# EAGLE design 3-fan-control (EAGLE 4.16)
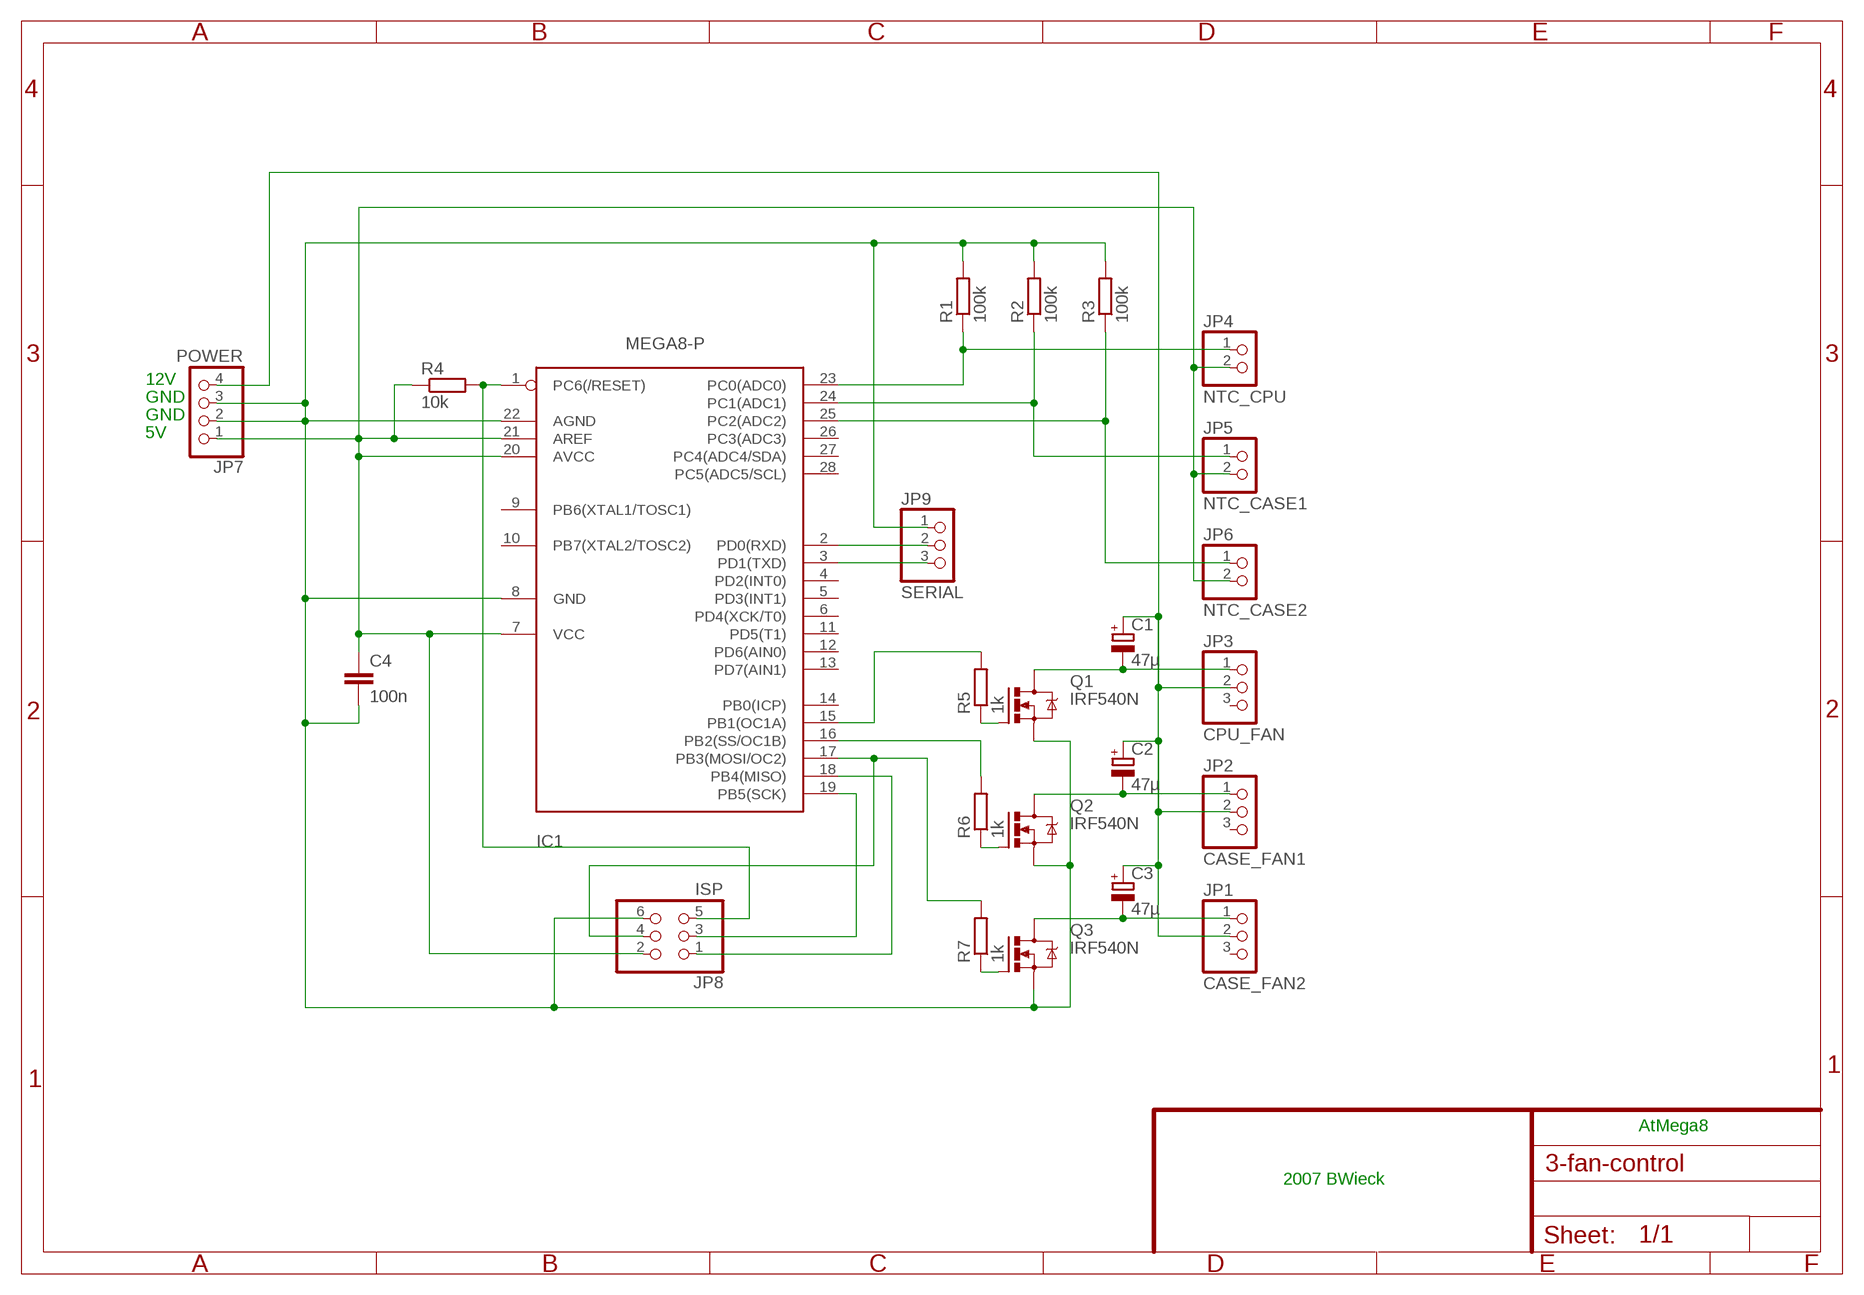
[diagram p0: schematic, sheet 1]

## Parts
C1  47µ  CPOL-EUE5-10.5  [E5-10,5]
C2  47µ  CPOL-EUE5-10.5  [E5-10,5]
C3  47µ  CPOL-EUE5-10.5  [E5-10,5]
C4  100n  C-EU050-024X044  [C050-024X044]
IC1  MEGA8-P  [DIL28-3]
JP1  CASE_FAN2  PINHD-1X3  [1X03]
JP2  CASE_FAN1  PINHD-1X3  [1X03]
JP3  CPU_FAN  PINHD-1X3  [1X03]
JP4  NTC_CPU  PINHD-1X2  [1X02]
JP5  NTC_CASE1  PINHD-1X2  [1X02]
JP6  NTC_CASE2  PINHD-1X2  [1X02]
JP7  POWER  PINHD-1X4  [1X04]
JP8  ISP  PINHD-2X3  [2X03]
JP9  SERIAL  PINHD-1X3  [1X03]
Q1  IRF540N  IRF740  [TO220BV]
Q2  IRF540N  IRF740  [TO220BV]
Q3  IRF540N  IRF740  [TO220BV]
R1  100k  R-EU_0207/10  [0207/10]
R2  100k  R-EU_0207/10  [0207/10]
R3  100k  R-EU_0207/10  [0207/10]
R4  10k  R-EU_0207/10  [0207/10]
R5  1k  R-EU_0207/10  [0207/10]
R6  1k  R-EU_0207/10  [0207/10]
R7  1k  R-EU_0207/10  [0207/10]

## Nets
N$1: C4.1 IC1.7(VCC) IC1.20(AVCC) IC1.21(AREF) JP4.2 JP5.2 JP6.2 JP7.1 JP8.2 R4.1
N$2: IC1.15(PB1(OC1A)) R5.2
N$3: IC1.1(PC6(/RESET)) JP8.5 R4.2
N$4: Q3.G R7.1
N$5: IC1.23(PC0(ADC0)) JP4.1 R1.1
N$6: IC1.24(PC1(ADC1)) JP5.1 R2.1
N$7: IC1.25(PC2(ADC2)) JP6.1 R3.1
N$8: C4.2 IC1.8(GND) IC1.22(AGND) JP7.2 JP7.3 JP8.6 JP9.1 Q1.S Q2.S Q3.S R1.2 R2.2 R3.2
N$9: C1.+ C2.+ C3.+ JP1.2 JP2.2 JP3.2 JP7.4
N$10: C1.- JP3.1 Q1.D
N$11: C2.- JP2.1 Q2.D
N$12: C3.- JP1.1 Q3.D
N$13: IC1.18(PB4(MISO)) JP8.1
N$14: IC1.19(PB5(SCK)) JP8.3
N$15: IC1.16(PB2(SS/OC1B)) R6.2
N$16: Q1.G R5.1
N$18: Q2.G R6.1
N$19: IC1.17(PB3(MOSI/OC2)) JP8.4 R7.2
N$21: IC1.3(PD1(TXD)) JP9.3
N$22: IC1.2(PD0(RXD)) JP9.2
Unconnected: IC1.4(PD2(INT0)) IC1.5(PD3(INT1)) IC1.6(PD4(XCK/T0)) IC1.9(PB6(XTAL1/TOSC1)) IC1.10(PB7(XTAL2/TOSC2)) IC1.11(PD5(T1)) IC1.12(PD6(AIN0)) IC1.13(PD7(AIN1)) IC1.14(PB0(ICP)) IC1.26(PC3(ADC3)) IC1.27(PC4(ADC4/SDA)) IC1.28(PC5(ADC5/SCL)) JP1.3 JP2.3 JP3.3

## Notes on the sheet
- 12V
- GND
- GND
- 5V
- AtMega8
- 2007 BWieck

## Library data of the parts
C1-C3 = rcl:CPOL-EU: POLARIZED CAPACITOR, European symbol
C4 = rcl:C-EU: CAPACITOR, European symbol
IC1 = atmel:MEGA8-P: MICROCONTROLLER 8 Kbytes FLASH 1 kbytes SRAM 512 bytes EEPROM USART 4-channel 10 bit ADC 2-channel 8 bit ADC
JP1-JP3 JP9 = pinhead:PINHD-1X3: PIN HEADER
JP4-JP6 = pinhead:PINHD-1X2: PIN HEADER
JP7 = pinhead:PINHD-1X4: PIN HEADER
JP8 = pinhead:PINHD-2X3: PIN HEADER
Q1-Q3 = transistor-power:IRF740: N-CHANNEL MOS FET
R1-R7 = rcl:R-EU_: RESISTOR, European symbol

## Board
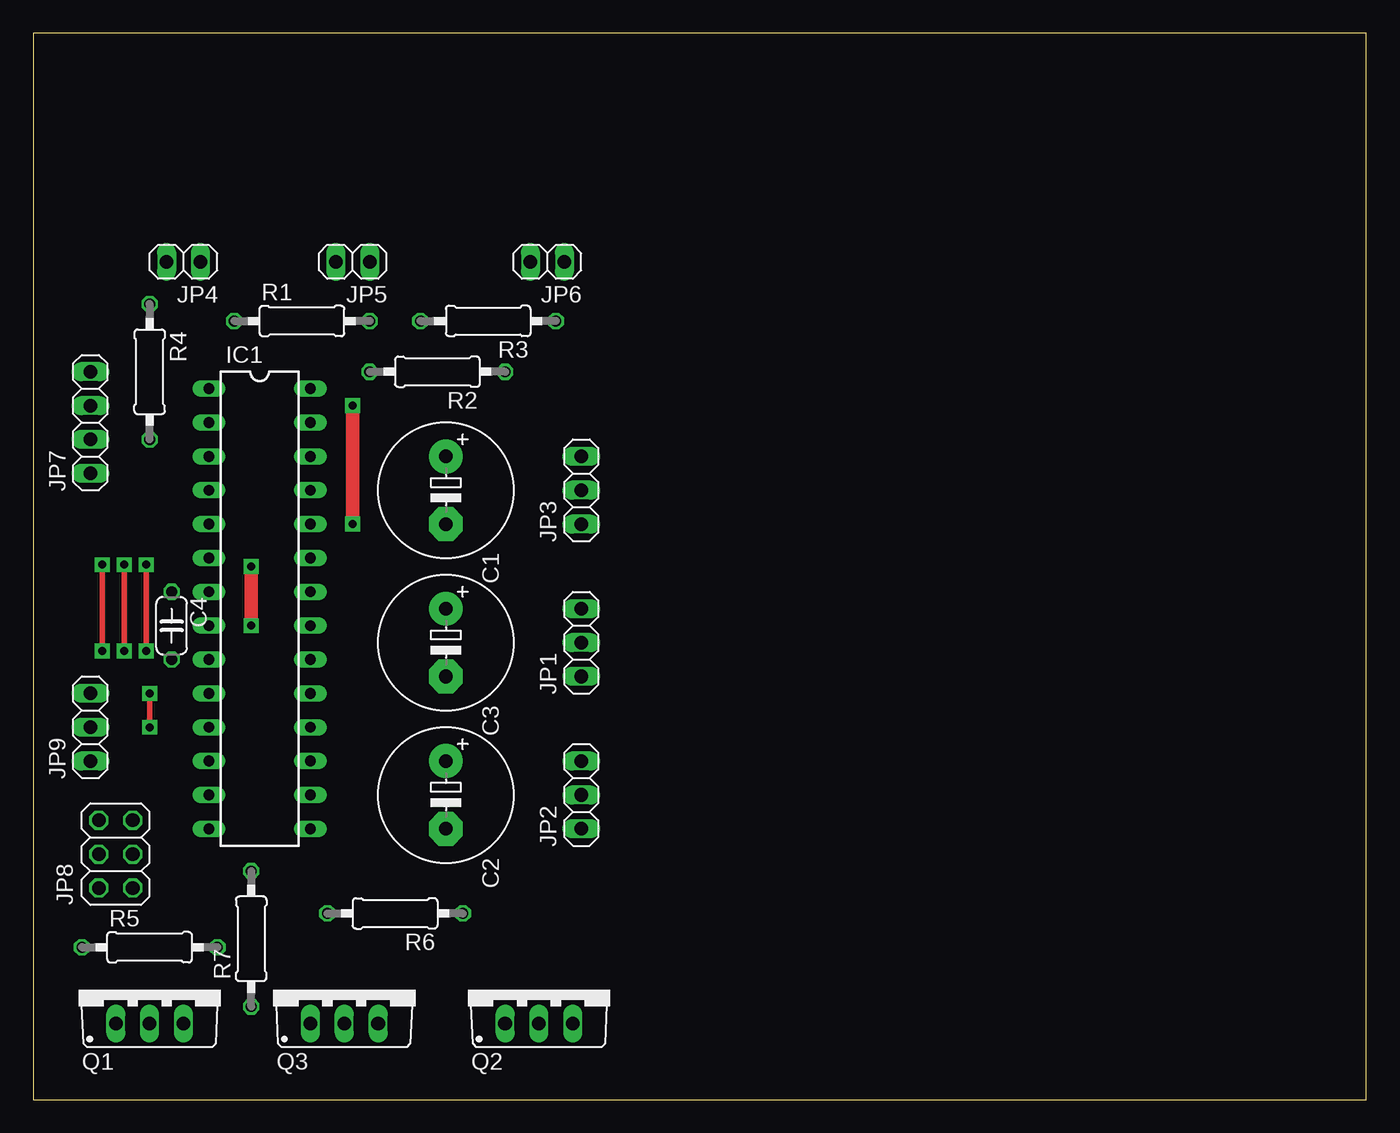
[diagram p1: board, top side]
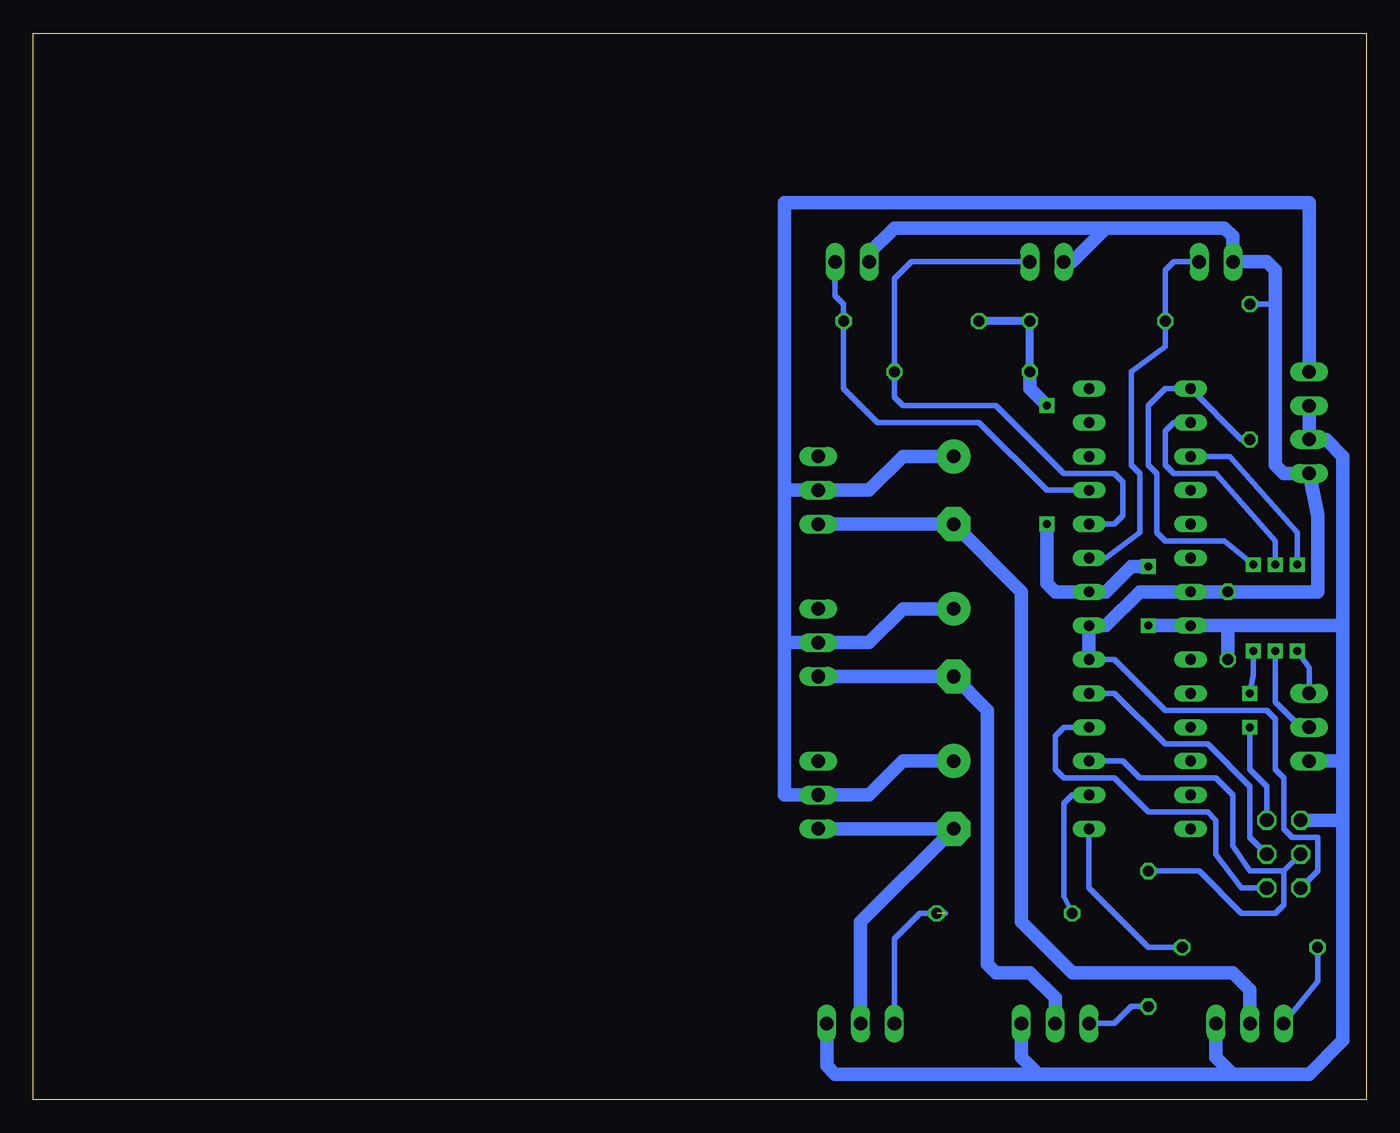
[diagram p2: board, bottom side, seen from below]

Size 100 x 80 mm. Coordinates in mm from the lower left corner, seen from the top.
Outline: 0,0 100,0 100,80 0,80 0,0
Copper layers (1*16): Top 0.035mm / dielectric 1.5mm / Bottom 0.035mm
Design rules "PCB-POOL": minimum track width 6mil, minimum drill 12mil, track to track 6mil, track to pad 6mil, pad to pad 6mil, via to via 6mil, smd to smd 6mil, copper to edge 20mil, drill to drill 8mil, minimum pad ring 8mil, minimum via ring 10mil, stop-mask expansion 3mil, vias tented up to drill 0mil, thermal gap 8mil

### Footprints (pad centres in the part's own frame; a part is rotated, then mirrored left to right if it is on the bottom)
E5-10,5 = drill 1.016 pad 2.54 round: + -2.54,0 | drill 1.016 pad 2.54 octagon: - 2.54,0
C050-024X044 = drill 0.813 octagon: 1 -2.54,0; 2 2.54,0
DIL28-3 = drill 0.813 long: 1 -16.51,-3.81; 2 -13.97,-3.81; 3 -11.43,-3.81; 4 -8.89,-3.81; 5 -6.35,-3.81; 6 -3.81,-3.81; 7 -1.27,-3.81; 8 1.27,-3.81; 9 3.81,-3.81; 10 6.35,-3.81; 11 8.89,-3.81; 12 11.43,-3.81; 13 13.97,-3.81; 14 16.51,-3.81; 15 16.51,3.81; 16 13.97,3.81; 17 11.43,3.81; 18 8.89,3.81; 19 6.35,3.81; 20 3.81,3.81; 21 1.27,3.81; 22 -1.27,3.81; 23 -3.81,3.81; 24 -6.35,3.81; 25 -8.89,3.81; 26 -11.43,3.81; 27 -13.97,3.81; 28 -16.51,3.81
1X03 = drill 1.016 long: 1 -2.54,0; 2 0,0; 3 2.54,0
1X02 = drill 1.016 long: 1 -1.27,0; 2 1.27,0
1X04 = drill 1.016 long: 1 -3.81,0; 2 -1.27,0; 3 1.27,0; 4 3.81,0
2X03 = drill 1.016 octagon: 1 -2.54,-1.27; 2 -2.54,1.27; 3 0,-1.27; 4 0,1.27; 5 2.54,-1.27; 6 2.54,1.27
TO220BV = drill 1.016 long: D 0,-2.54; G -2.54,-2.54; S 2.54,-2.54
0207/10 = drill 0.813 octagon: 1 -5.08,0; 2 5.08,0

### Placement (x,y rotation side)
C1  30.95,45.72 270 top
C2  30.95,22.86 270 top
C3  30.95,34.29 270 top
C4  10.38,35.55 270 top
IC1  16.98,36.83 270 top
JP1  41.11,34.29 90 top
JP2  41.11,22.86 90 top
JP3  41.11,45.72 90 top
JP4  11.27,62.86 180 top
JP5  23.96,62.86 180 top
JP6  38.57,62.86 180 top
JP7  4.28,50.8 90 top
JP8  6.18,18.41 90 top
JP9  4.28,27.93 90 top
Q1  8.73,8.25 0 top
Q2  37.94,8.25 0 top
Q3  23.33,8.25 0 top
R1  20.15,58.41 0 top
R2  30.31,54.61 180 top
R3  34.12,58.41 180 top
R4  8.73,54.61 270 top
R5  8.73,11.43 0 top
R6  27.14,13.97 180 top
R7  16.34,12.06 90 top

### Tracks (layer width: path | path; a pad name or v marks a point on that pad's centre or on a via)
N$1
  Bottom 0.406: JP8.2 3.64,17.14 3.64,19.68 5.55,19.68 6.18,20.31 6.18,24.12 6.82,24.76 6.82,28.57 7.46,29.2 15.08,29.2 18.88,33.02 IC1.20 | 6.82,59.69 R4.1
  Bottom 1.016: IC1.20 IC1.21 19.52,35.55 16.98,38.1 IC1.7 C4.1 3.64,38.1 3.64,43.81 JP7.1 6.18,46.98 6.82,47.62 6.82,59.69 6.82,62.23 7.46,62.86 JP4.2 10,64.77 10.63,65.4 19.52,65.4 | JP5.2 22.06,62.86 19.52,65.4 | JP6.2 37.3,63.5 35.39,65.4 19.52,65.4
N$2
  Bottom 0.406: R5.2 16.34,11.43 20.79,15.87 IC1.15
N$3  (via drill 0.6)
  Top 0.406: v8.47,33.65 v8.47,40.13 | v8.73,27.93 v8.73,30.47
  Bottom 0.406: v8.47,40.13 10.63,41.91 15.08,41.91 15.71,42.54 15.71,46.98 16.34,47.62 16.34,52.07 15.08,53.34 IC1.1 9.36,49.53 R4.2 | v8.47,33.65 8.47,31.87 v8.73,30.47 | v8.73,27.93 8.73,24.76 7.46,23.49 JP8.5
N$4
  Bottom 0.406: Q3.G 18.88,5.71 17.61,6.98 R7.1
N$5
  Bottom 0.406: JP4.1 14.44,62.86 15.08,62.23 R1.1 15.08,56.51 17.61,54.61 17.61,47.62 16.98,46.98 16.98,42.54 19.52,40.64 IC1.23
N$6
  Bottom 0.406: JP5.1 34.12,62.86 35.39,61.59 R2.1 35.39,52.7 34.76,52.07 27.77,52.07 22.7,46.98 18.88,46.98 18.25,46.35 18.25,43.81 18.88,43.18 IC1.24
N$7
  Bottom 0.406: JP6.1 39.84,60.32 39.2,59.69 R3.1 39.2,53.34 36.66,50.8 29.04,50.8 23.96,45.72 IC1.25
N$8  (via drill 0.6)
  Top 1.016: v16.34,35.55 v16.34,40 | v23.96,43.18 v23.96,52.07
  Bottom 0.61: R3.2 R1.2 R2.2
  Bottom 1.016: JP7.3 JP7.2 3.01,49.53 1.74,48.26 1.74,35.55 | 1.74,20.95 1.74,25.39 | 1.74,25.39 JP9.1 | 1.74,20.95 JP8.6 | 1.74,25.39 1.74,35.55 | 1.74,35.55 10.38,35.55 | 10.38,35.55 IC1.8 v16.34,35.55 | 10.38,35.55 C4.2 | 1.74,20.95 1.74,4.44 4.28,1.9 10,1.9 | 10,1.9 11.27,3.17 Q1.S | Q3.S 25.87,3.17 24.6,1.9 | 10,1.9 24.6,1.9 | Q2.S 40.48,2.54 39.84,1.9 24.6,1.9 | v16.34,40 17.61,40 19.52,38.1 IC1.22 23.33,38.1 23.96,38.73 v23.96,43.18 | R2.2 25.23,53.34 v23.96,52.07
N$9
  Bottom 1.016: 43.65,45.72 JP3.2 37.3,45.72 34.76,48.26 C1.+ | 43.65,34.29 43.65,45.72 | 43.65,34.29 JP1.2 37.3,34.29 34.76,36.83 C3.+ | 43.65,34.29 43.65,22.86 JP2.2 37.3,22.86 34.76,25.39 C2.+ | JP7.4 4.28,67.3 43.65,67.3 43.65,45.72
N$10
  Bottom 1.016: JP3.1 C1.- 25.87,38.1 25.87,13.33 22.06,9.52 10,9.52 8.73,8.25 Q1.D
N$11
  Bottom 1.016: JP2.1 C2.- 37.94,13.33 Q2.D
N$12
  Bottom 1.016: JP1.1 C3.- 28.41,29.2 28.41,10.16 27.77,9.52 25.23,9.52 23.33,7.62 Q3.D
N$13
  Bottom 0.406: JP8.1 9.36,15.87 11.27,18.41 11.27,20.95 11.9,21.58 16.34,21.58 18.88,24.12 22.7,24.12 23.33,24.76 23.33,27.3 22.7,27.93 IC1.18
N$14
  Bottom 0.406: JP8.3 8.73,19.68 8.73,23.49 11.9,26.66 15.08,26.66 18.88,30.47 IC1.19
N$15
  Bottom 0.406: R6.2 22.7,15.24 22.7,22.22 22.06,22.86 IC1.16
N$16
  Bottom 0.406: Q1.G 3.64,8.89 R5.1
N$18  (1 unrouted)
  Bottom 0.406: Q2.G 35.39,12.06 33.49,13.97 31.58,13.97
N$19
  Bottom 0.406: 6.18,17.14 JP8.4 | 6.18,17.14 8.73,17.14 10,19.04 10,22.86 11.27,24.12 16.98,24.12 18.25,25.39 IC1.17 | R7.2 12.54,17.14 9.36,13.97 6.82,13.97 6.18,14.6 6.18,17.14
N$21  (via drill 0.6)
  Top 0.406: v5.17,33.65 v5.17,40.13
  Bottom 0.406: JP9.3 4.28,32.38 v5.17,33.65 | v5.17,40.13 5.17,42.54 10.25,48.26 IC1.3
N$22  (via drill 0.6)
  Top 0.406: v6.82,33.65 v6.82,40.13
  Bottom 0.406: JP9.2 4.92,27.93 6.82,29.84 v6.82,33.65 | v6.82,40.13 6.82,41.91 11.27,46.98 14.44,46.98 15.08,47.62 15.08,50.16 14.44,50.8 IC1.2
